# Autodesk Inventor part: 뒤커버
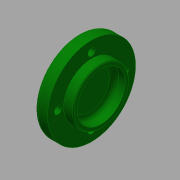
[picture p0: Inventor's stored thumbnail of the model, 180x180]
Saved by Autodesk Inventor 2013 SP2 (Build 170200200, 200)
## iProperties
Created: 2015-12
Part Number: 뒤커버
Material: 일반
Document SubType Name: Modeling
Designer: mduedu
Density: 1 g/cm^3
Author: mduedu
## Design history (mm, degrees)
sketch "스케치1"
  geometry: L1 (0, 0)-(14, 0); L2 (14, 0)-(14, 17.5); L3 (14, 17.5)-(8, 17.5); L4 (8, 17.5)-(8, 27.5); L5 (8, 27.5)-(0, 27.5); L6 (0, 27.5)-(0, 0)
  constraints: 12 end point, 4 parallel, 1 horizontal, 1 perpendicular
  dimensions: "d0" = 14 distance between parallel lines of L2 L6; "d2" = 8 distance of L4.end L5.end; "d3" = 55 diameter of L5 L1; "d4" = 35 diameter of L3 L1
revolve "회전1" sketch "스케치1" stored, may be unused: angle "d5" = 90 deg
hole "구멍1" diameter "d8" = 30; stored, may be unused: countersink angle "d12" = 90 deg, drill point angle "d14" = 0 deg; dims "d9" = 6, "d10" = 4, "d11" = 2, "d13" = 7, "d39" = 10, "d40" = 10
fillet "모깎기3" dims "d38" = 2
fillet "모깎기4" dims "d41" = 3
chamfer "모따기2" distance "d42" = 0.5; stored, may be unused: second distance "d43" = 2, angle "d44" = 45 deg
sketch "스케치2" dims "d45" = 42
  geometry: 6 further points
  constraints: 2 vertical alignment, 1 coincident, 7 other
  dimensions: "d48" = 360 deg dimension on point (0, 0) point (0, 21) (derived)
sketch "스케치3"
  geometry: 4 further points
hole "구멍4" sketch "스케치3" at (-21, 0), (0, -21), (21, 0), (0, 21) diameter "d50" = 4.5; stored, may be unused: countersink angle "d54" = 90 deg, drill point angle "d56" = 0 deg; dims "d51" = 6, "d52" = 8, "d53" = 4.6, "d55" = 8
node "솔리드1"
